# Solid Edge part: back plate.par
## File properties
Author: Deepak Maini
Template: normal.par
Last saved by: Robert a Rhodes jr
Revision: 11
Application: Solid Edge
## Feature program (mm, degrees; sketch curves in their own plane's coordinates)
sketch for "unnamed RevolvedProtrusion 1" plane through (0, 0, 0) normal (0, 0, 1) x-axis (1, 0, 0)
  line (0, 58.528) -> (50, 58.528)
  line (50, 58.528) -> (50, 36.528)
  line (50, 36.528) -> (77.5, 36.528)
  line (77.5, 36.528) -> (77.5, 15.528)
  line (77.5, 15.528) -> (0, 15.528)
  line (0, 15.528) -> (0, 58.528)
revolve "unnamed RevolvedProtrusion 1" add finite 360 deg
sketch for "unnamed Protrusion 1" plane through (0, 0, 0) normal (0, 0, 1) x-axis (1, 0, 0)
  line (-25.2075, 15.528) -> (-35, -5.472)
  line (-35, -5.472) -> (35, -5.472)
  line (35, -5.472) -> (25.2075, 15.528)
  line (25.2075, 15.528) -> (-25.2075, 15.528)
extrude "unnamed Protrusion 1" add finite 247.65 symmetric
sketch for "unnamed Cutout 1" plane through (0, 36.528, 0) normal (0, 1, 0) x-axis (0, 0, -1)
  circle centre (0, 0) radius 77.5
extrude "unnamed Cutout 1" cut through along -normal
sketch for "unnamed Cutout 2" #1 plane through (-51.3538, 15.528, 0) normal (0, -1, 0) x-axis (0, 0, 1)
  line (-59.2136, -101.3538) -> (59.2136, -101.3538)
  arc centre (0, -51.3538) radius 77.5 from (59.2136, -101.3538) to (-59.2136, -101.3538) cw
sketch for "unnamed Cutout 2" #2 plane through (-51.3538, 15.528, 0) normal (0, -1, 0) x-axis (0, 0, 1)
  line (-59.2136, -1.3538) -> (59.2136, -1.3538)
  arc centre (0, -51.3538) radius 77.5 from (-59.2136, -1.3538) to (59.2136, -1.3538) cw
extrude "unnamed Cutout 2" cut finite 1 along -normal
sketch for "unnamed Cutout 3" plane through (0, 0, 77.5) normal (0, 0, 1) x-axis (1, 0, 0)
  line (-20, -5.472) -> (-20, 5.528)
  arc centre (0, 5.528) radius 20 from (-20, 5.528) to (20, 5.528) cw
  line (20, 5.528) -> (20, -5.472)
  line (20, -5.472) -> (-20, -5.472)
extrude "unnamed Cutout 3" cut finite 40 along -normal
sketch for "unnamed Cutout 4" plane through (0, 0, 0) normal (0, 0, 1) x-axis (1, 0, 0)
  line (14, 5.528) -> (14, -5.472)
  arc centre (0, 5.528) radius 14 from (-14, 5.528) to (14, 5.528) cw
  line (-14, -5.472) -> (-14, 5.528)
  line (-14, -5.472) -> (14, -5.472)
extrude "unnamed Cutout 4" cut through along -normal
sketch for "unnamed Cutout 5" plane through (0, -5.472, -0.1655) normal (0, -1, 0) x-axis (0, 0, -1)
  circle centre (-0.1655, 0) radius 22.5
extrude "unnamed Cutout 5" cut along +normal
sketch for "unnamed Cutout 6" plane through (0, 36.528, 0) normal (0, -1, 0) x-axis (1, 0, 0)
  circle centre (0, 0) radius 11
extrude "unnamed Cutout 6" cut through along -normal
sketch for "unnamed Cutout 7" plane through (0, 5.028, 37.5) normal (0, 0, 1) x-axis (1, 0, 0)
  circle centre (0, 0.5) radius 8
extrude "unnamed Cutout 7" cut through along -normal
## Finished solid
Body 1: solid body, 24 faces, 56 edges, 32 vertices.
  Faces by surface: plane 17, cylinder 7
  Edges by curve: line 29, circle 19, ellipse 4, intersection 4
Bounding box of the edges (mm): 155.000 x 64.000 x 155.000, from (-77.5, -5.472, -77.5) to (77.5, 58.528, 77.5).
Cylindrical faces by radius (mm): R8 x1, R11 x1, R14 x1, R20 x1, R22.5 x1, R50 x1, R77.5 x1
Planar faces by outward normal: +x 3, +y 2, +z 1, -x 3, -y 6, oblique 2
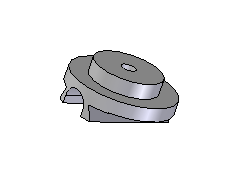
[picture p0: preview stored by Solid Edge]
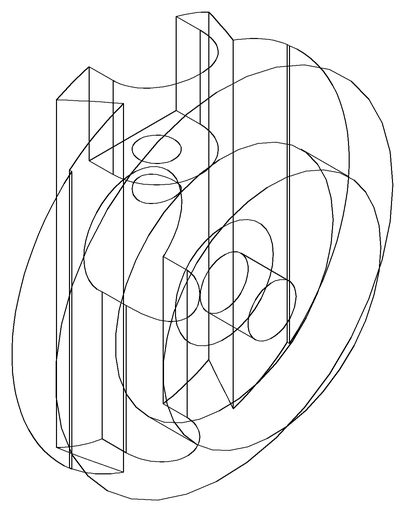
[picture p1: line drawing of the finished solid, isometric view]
